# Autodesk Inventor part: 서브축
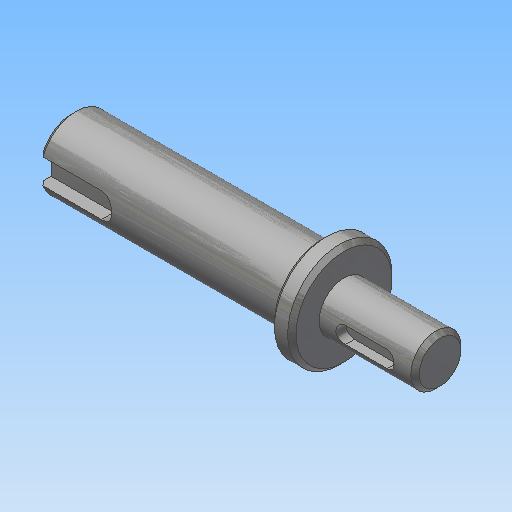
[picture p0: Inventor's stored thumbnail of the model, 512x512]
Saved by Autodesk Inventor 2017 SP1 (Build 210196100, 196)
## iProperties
Created: 2018-09
Part Number: 서브축
Document SubType Name: Modeling
Density: 7.86 g/cm^3
Material: 강철, 연강
Appearance: 강철
Mass: 142.801 g
Surface Area: 54.794 cm^2
Volume: 18.1681 cm^3
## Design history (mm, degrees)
sketch "스케치1"
  geometry: L1 (-18.818, -7)-(-18.818, 7) reference; L2 (-41.331, -13.5)-(-41.331, 13.5) reference; L3 (-46.5, 12.249)-(-46.5, -12.249) reference; L4 (-18.331, 0)-(-106.5, 0); L5 (-18.331, 0)-(-18.331, -6); L6 (-18.331, -6)-(-41.331, -6); L7 (-41.331, -12.5)-(-46.5, -12.5); L8 (-46.5, -8.5)-(-106.5, -8.5); L9 (-106.5, -8.5)-(-106.5, 0); L10 (-46.5, -8.5)-(-46.5, -12.5); L11 (-41.331, -6)-(-41.331, -12.5); 2 further points
  constraints: 17 end point, 5 point on line, 3 parallel, 3 perpendicular, 2 collinear, 1 midpoint
  dimensions: "d0" = 23 distance between parallel lines of L2 L5; "d1" = 12 diameter of L6 L4; "d2" = 25 diameter of L7 L4; "d3" = 17 diameter of L8 L4; "d4" = 60 distance of L8.start L8.end
revolve "회전1" sketch "스케치1" stored, may be unused: angle "d5" = 90 deg
chamfer "모따기1" distance "d6" = 1; stored, may be unused: second distance "d7" = 2, angle "d8" = 45 deg
node "작업 평면1"
sketch "스케치2"
  geometry: L1 (11.5, 5)-(11.5, -5) reference; L2 (-5.5, -2)-(4.5, -2); L3 (4.5, 2)-(-5.5, 2); A1 r 2 centre (4.5, 0) between (4.5, -2) and (4.5, 2); A2 r 2 centre (-5.5, 0) between (-5.5, 2) and (-5.5, -2); 2 further points
  constraints: 4 end point, 4 point on circle, 4 tangent, 2 centre point, 1 horizontal alignment, 1 midpoint, 1 parallel, 1 perpendicular
  dimensions: "d9" = 4 distance between parallel lines of L2 L3; "d10" = 14 dimension on A1 A2; "d11" = 5 distance edge to line of A1 L1
extrude "돌출1" cut sketch "스케치2" distance "d12" = 2.5; taper "d13" = 0 deg
node "작업 평면2"
sketch "스케치3"
  geometry: L1 (-30, -7.5)-(-30, 7.5) reference; L2 (-30, 3)-(-15, 3); L3 (-15, -3)-(-30, -3); A1 r 3 centre (-15, 0) between (-15, -3) and (-15, 3); 2 further points
  constraints: 4 end point, 2 perpendicular, 2 point on circle, 2 point on line, 2 tangent, 1 centre point, 1 horizontal alignment, 1 midpoint
  dimensions: "d14" = 6 distance between parallel lines of L3 L2; "d15" = 18 dimension on A1 L1
extrude "돌출2" cut sketch "스케치3" distance "d16" = 3.5; taper "d17" = 0 deg
node "솔리드1"
node "참조1"
node "참조2"
node "참조3"
